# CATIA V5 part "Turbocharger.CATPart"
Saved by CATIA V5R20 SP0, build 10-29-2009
Part number: Assem_charger.SLDASM
Bounding box of the stored display mesh (mm): x -585.532 to 603.57, y -580.393 to 558.175, z -447.839 to 487.412
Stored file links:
  C:\Users\Mech\Desktop\Turbocharger.CATPart

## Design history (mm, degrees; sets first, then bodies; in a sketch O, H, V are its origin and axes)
Set1
  DatumSurface1 to DatumSurface848
Body1 (main body)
